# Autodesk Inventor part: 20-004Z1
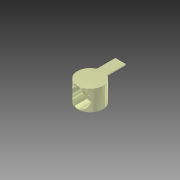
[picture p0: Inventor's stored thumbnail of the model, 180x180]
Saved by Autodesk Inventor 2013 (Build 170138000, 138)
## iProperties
Created: 2004-10
Part Number: 20-004Z1
Material: Zinc ZA-12
Document SubType Name: Modeling
Designer: Autodesk, Inc.
Manufacturer: Standard
Standards Organization: Custom
Description: FASTENER, 40 SERIES, UNIVERSAL
Catalog Web Link: http://www.parker.com/ead/cm1.asp?cmid=809
Vendor: PARKER IPS
Mass: 17.4422 g
Surface Area: 24.0595 cm^2
Volume: 2.88778 cm^3
Density: 6.04 g/cm^3
CAGE: 1LJX3
Dept. ID: Product Design
Description #2: ---
Finish #1: ---
Finish #2: ---
Material ID: ---
Project Number: ---
Author: Autodesk, Inc.
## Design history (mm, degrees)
derived "2X-YYY Universal Fastner.ipt"
body "Solid1"
tag "TaggingFeature2"
feature "Solid1::2X-YYY Universal Fastner.ipt"
other parameters: "d47" = 0, "d48" = 0
